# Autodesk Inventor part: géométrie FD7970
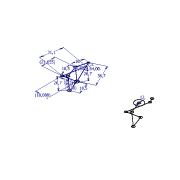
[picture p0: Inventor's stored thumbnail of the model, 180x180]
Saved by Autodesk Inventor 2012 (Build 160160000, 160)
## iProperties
Created: 2011-11
Part Number: géométrie FD7970
Document SubType Name: Modeling
Designer: Laur
Density: 1 g/cm^3
Material: Par défaut
Author: Laur
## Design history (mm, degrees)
sketch "Esquisse1"
  geometry: L1 (278.781, -104.353)-(284.654, -6.929); L2 (284.654, -6.929)-(326.872, -9.474); L3 (326.872, -9.474)-(320.998, -106.898); L4 (320.998, -106.898)-(278.781, -104.353); L5 (-37.691, 5.884)-(39.021, 1.997); L6 (39.021, 1.997)-(37.087, -36.195); L7 (37.087, -36.195)-(-39.625, -32.309); L8 (-39.625, -32.309)-(-37.691, 5.884); L9 (450.184, -16.898)-(444.463, -96.06) reference; L10 (444.463, -96.06)-(405.527, -93.247); L11 (405.527, -93.247)-(411.247, -14.084); L12 (411.247, -14.084)-(450.184, -16.898) reference; L13 (38.92, 0)-(0, 0); L14 (0, 0)-(0, -13.458); L15 (-13.374, -4.322)-(19.75, -20.122); L16 (19.75, -20.122)-(4.255, -24.107); L17 (4.255, -24.107)-(-13.374, -4.322); L18 (-31.711, -6.777)-(-13.374, -4.322); L19 (4.255, -24.107)-(-14.082, -26.562); L20 (-31.711, -6.777)-(-14.082, -26.562); L21 (-13.374, -4.322)-(-6.026, -21.952); L22 (57.013, 4.557)-(57.013, -33.913); L23 (89.022, -33.355)-(84.425, -51.275); L24 (104.427, -68.961)-(84.425, -51.275); L25 (104.427, -68.961)-(109.024, -51.042); L26 (109.024, -51.042)-(91.918, -43.996); L27 (89.022, -33.355)-(109.024, -51.042); L28 (109.024, -51.042)-(93.224, -17.917) reference; L29 (93.224, -17.917)-(89.022, -33.355); L30 (74.805, -79.41)-(127.709, -79.41); L31 (127.709, -79.41)-(127.709, -87.106); L32 (127.709, -87.106)-(74.805, -87.106); L33 (74.805, -87.106)-(74.805, -79.41); L34 (185.107, -90.458)-(185.107, -79.35); L35 (185.107, -79.35)-(238.012, -79.35); L36 (238.012, -79.35)-(238.012, -90.458); L37 (238.012, -90.458)-(185.107, -90.458); L38 (222.335, -68.41)-(215.972, -51.039); L39 (222.335, -68.41)-(202.333, -50.724); L40 (215.972, -51.039)-(197.884, -54.923); L41 (195.97, -33.353)-(202.333, -50.724); L42 (215.972, -51.039)-(200.172, -17.914) reference; L43 (200.172, -17.914)-(195.97, -33.353); L44 (195.97, -33.353)-(215.972, -51.039); L45 (269.3, -80.6)-(269.3, -53.445); L46 (428.304, -32.227)-(422.456, -36.254); L47 (428.304, -32.227)-(420.544, -62.343); L48 (397.895, -41.969)-(397.895, -33.863); L49 (283.808, 9.579)-(278.087, -69.583) reference; L50 (197.884, -54.923)-(203.284, -24.296); L51 (203.284, -24.296)-(200.172, -17.914); L52 (297.728, -27.199)-(303.694, -23.091); L53 (303.694, -23.091)-(295.408, -53.56); L54 (91.918, -43.996)-(98.934, -13.697); L55 (98.934, -13.697)-(93.224, -17.917); L56 (77.02, -96.95)-(237.761, -96.95); L57 (237.761, -96.95)-(237.761, -125.922); L58 (237.761, -125.922)-(77.02, -125.922); L59 (77.02, -125.922)-(77.02, -96.95); C1 r 2.73 at (-13.374, -4.322); C2 r 1.542 at (19.75, -20.122); C3 r 1.924 at (4.255, -24.107); C4 r 2.077 at (-31.711, -6.777); C5 r 1.999 at (-14.082, -26.562); C6 r 1.766 at (-6.026, -21.952); C7 r 1.924 at (89.022, -33.355); C8 r 2.73 at (109.024, -51.042); C9 r 1.999 at (84.425, -51.275); C10 r 2.077 at (104.427, -68.961); C11 r 1.766 at (91.918, -43.996); C12 r 1.542 at (93.224, -17.917); C13 r 2.73 at (215.972, -51.039); C14 r 1.999 at (202.333, -50.724); C15 r 2.077 at (222.335, -68.41); C16 r 1.766 at (197.884, -54.923); C17 r 1.924 at (195.97, -33.353); C18 r 1.542 at (200.172, -17.914); C19 r 1.783 at (295.408, -53.56); C20 r 1.842 at (428.304, -32.227); C21 r 1.928 at (420.544, -62.343); C22 r 1.601 at (422.456, -36.254); C23 r 1.818 at (293.719, -42.271); C24 r 1.92 at (418.558, -50.912); 1 further point; 3 other entities
  constraints: 68 end point, 24 centre point, 2 parallel, 1 coincident, 1 horizontal, 1 perpendicular, 1 point on line, 1 vertical, 21 other
  dimensions: "d12" = 26.5 distance of L16.end L15.start; "d13" = 36.7 distance of L15.end L15.start; "d14" = 16 distance of L16.end L15.end; "d38" = 18.5 distance of L15.start L18.start; "d39" = 18.5 distance of L16.end L19.end; "d40" = 26.5 distance of L19.end L18.start; "d41" = 2.9 deg angle of L5 L13; "d47" = 13.3744 distance from line of L14 L15.start; "d49" = 4.32194 distance from line of L15.start L13; "d52" = 25.5 deg angle of L15 L13; "d71" = 19.1 distance of L21.end L15.start; "d72" = 105 deg angle of L18 L21; "d122" = 34.3062 vertical distance of L7.end L5.end; "d148" = 16 distance of L23.start L28.end; "d149" = 26.7 distance of L25.end L23.start; "d150" = 26.7 distance of L24.start L23.end; "d151" = 18.5 distance of L23.end L23.start; "d152" = 18.5 distance of L24.start L25.end; "d154" = 36.7 distance of L28.end L25.end; "d155" = 18.5 distance of L25.end L26.end; "d186" = 16 distance of L41.start L42.end; "d187" = 26.7 distance of L38.end L41.start; "d188" = 26.7 distance of L38.start L39.end; "d189" = 18.5 distance of L39.end L41.start; "d190" = 18.5 distance of L38.start L38.end; "d191" = 36.7 distance of L42.end L38.end; "d192" = 18.5 distance of L38.end L40.end; "d200" = 3.45 deg angle of L3 L45; "d230" = 97.42345 vertical distance of L3.end L2.end; "d270" = 31.1 distance of L47.end L46.start; "d274" = 7.1 distance of L46.start L46.end; "d276" = 14.45 deg angle of L47 L48; "d278" = 41 deg angle of L47 L46; "d286" = 31.1 distance of L50.end L40.end; "d291" = 7.1 distance of L42.end L50.end; "d292" = 19.78535 vertical distance of L16.end L15.start (derived); "d304" = 40.2361 deg angle of L53 L52; "d307" = 11.41518 distance of L53.end C23.centre; "d308" = 11.60219 distance of L47.end C24.centre; "d310" = 21.65541 distance of L40.end L41.start (derived); "d311" = 31.1 distance of L54.end L26.end; "d312" = 7.1 distance of L28.end L54.end; "d317" = 11.02761 distance of L26.end L23.start (derived); "d319" = 98 deg angle of L25 L26; "d320" = 39.8875 deg angle of L25 L28 (derived); "d321" = 98 deg angle of L38 L40; "d322" = 5.38054 deg angle of L38 L42 (derived); "d323" = 36 deg angle of L50 L51; "d324" = 139.5 deg angle of L54 L55; "d327" = 15.2139 deg angle of L45 L53; "d332" = 24.59875 horizontal distance of L23.end L25.end (derived); "d333" = 18.08767 horizontal distance of L40.end L38.end (derived); "d334" = 53.538 deg angle of L55 L22 (derived); "d337" = 154 deg angle of L51 L22 (derived)
  node "Image1"
  node "Image2"
  node "Image3"
sketch "pos grand plateau" dims "d597" = 12
  geometry: L1 (38.92, 0)-(0, 0); L2 (57.013, 4.557)-(57.013, -33.913); L3 (89.022, -33.355)-(84.425, -51.275); L4 (104.427, -68.961)-(84.425, -51.275); L5 (104.427, -68.961)-(109.024, -51.042); L6 (109.024, -51.042)-(91.918, -43.996); L7 (89.022, -33.355)-(109.024, -51.042); L8 (93.224, -17.917)-(89.022, -33.355); L9 (74.805, -79.41)-(127.709, -79.41); L10 (127.709, -79.41)-(127.709, -87.106); L11 (127.709, -87.106)-(74.805, -87.106); L12 (74.805, -87.106)-(74.805, -79.41); L13 (91.918, -43.996)-(98.934, -13.697); L14 (98.934, -13.697)-(93.224, -17.917); L15 (93.224, -17.917)-(129.229, -17.917); L16 (197.673, -37.138)-(203.902, -10.236); L17 (202.897, -9.569)-(199.93, -11.72); L18 (212.627, -45.195)-(198.906, -39.531); L19 (193.816, -30.061)-(190.132, -44.42); L20 (210.164, -61.991)-(213.847, -47.633); L21 (208.297, -62.564)-(191.009, -47.278); L22 (198.788, -32.172)-(198.817, -32.197); L23 (186.664, -56.328)-(194.774, -56.328); L24 (194.774, -56.328)-(197.613, -53.118); L25 (194.774, -56.328)-(194.774, -65.222); L26 (186.664, -56.328)-(186.664, -65.14); C1 r 1.924 at (89.022, -33.355); C2 r 2.73 at (109.024, -51.042); C3 r 1.999 at (84.425, -51.275); C4 r 2.077 at (104.427, -68.961); C5 r 1.766 at (91.918, -43.996); C6 r 1.542 at (93.224, -17.917); C7 r 1.72 at (98.934, -13.697); A1 r 1.72 centre (204.29, -8.559) between (202.897, -9.569) and (203.902, -10.236); A2 r 1.805 centre (214.295, -45.884) between (212.627, -45.195) and (213.847, -47.633); A3 r 1.766 centre (197.274, -38.858) between (197.673, -37.138) and (198.906, -39.531); A4 r 1.752 centre (189.697, -46.117) between (191.009, -47.278) and (190.132, -44.42); A5 r 1.871 centre (209.699, -63.804) between (210.164, -61.991) and (208.297, -62.564); 3 further points; 1 other entity
  constraints: 44 end point, 12 centre point, 10 point on circle, 4 perpendicular, 2 coincident, 2 point on line, 1 horizontal, 12 other
  dimensions: "d356" = 16 distance of L3.start L8.start; "d357" = 26.7 distance of L5.end L3.start; "d358" = 26.7 distance of L4.start L3.end; "d359" = 18.5 distance of L3.end L3.start; "d360" = 18.5 distance of L4.start L5.end; "d361" = 36.7 distance of L8.start L5.end; "d362" = 18.5 distance of L5.end L6.end; "d383" = 31.1 distance of L13.end L6.end; "d384" = 7.1 distance of L8.start L13.end; "d385" = 11.02761 distance of L6.end L3.start (derived); "d386" = 98 deg angle of L5 L6; "d391" = 139.5 deg angle of L13 L14; "d393" = 24.59875 horizontal distance of L3.end L5.end (derived); "d395" = 53.538 deg angle of L14 L2 (derived); "d571" = 36.462 deg angle of L15 L14
sketch "pos petit plateau"
  geometry: L1 (185.107, -90.458)-(185.107, -79.35); L2 (185.107, -79.35)-(238.012, -79.35); L3 (238.012, -79.35)-(238.012, -90.458); L4 (238.012, -90.458)-(185.107, -90.458); L5 (222.335, -68.41)-(215.972, -51.039); L6 (222.335, -68.41)-(202.333, -50.724); L7 (215.972, -51.039)-(197.884, -54.923); L8 (195.97, -33.353)-(202.333, -50.724); L9 (215.972, -51.039)-(200.172, -17.914) reference; L10 (200.172, -17.914)-(195.97, -33.353); L11 (195.97, -33.353)-(215.972, -51.039); L12 (197.884, -54.923)-(203.284, -24.296); L13 (203.284, -24.296)-(200.172, -17.914); L14 (200.172, -17.914)-(219.448, -17.914); L15 (315.228, -65.819)-(298.28, -50.833); L16 (316.07, -65.245)-(311.102, -51.685); L17 (308.484, -50.24)-(294.059, -53.338); L18 (291.081, -33.944)-(296.095, -47.632); L19 (292.64, -51.97)-(297.432, -24.79); L20 (296.973, -21.521)-(295.434, -18.366); C1 r 2.73 at (215.972, -51.039); C2 r 1.999 at (202.333, -50.724); C3 r 2.077 at (222.335, -68.41); C4 r 1.766 at (197.884, -54.923); C5 r 1.924 at (195.97, -33.353); C6 r 1.542 at (200.172, -17.914); C7 r 6 at (290.419, -32.138); A1 r 2.077 centre (316.784, -67.195) between (315.228, -65.819) and (316.07, -65.245); A2 r 1.766 centre (292.333, -53.708) between (292.64, -51.97) and (294.059, -53.338); A3 r 1.999 centre (296.782, -49.509) between (296.095, -47.632) and (298.28, -50.833); A4 r 1.981 centre (310.421, -49.824) between (308.484, -50.24) and (311.102, -51.685); A5 r 1.735 centre (297.733, -23.081) between (296.973, -21.521) and (297.432, -24.79); 2 further points; 1 other entity
  constraints: 32 end point, 12 centre point, 10 point on circle, 1 coincident, 1 parallel, 10 other
  dimensions: "d427" = 16 distance of L8.start L9.end; "d428" = 26.7 distance of L5.end L8.start; "d429" = 26.7 distance of L5.start L6.end; "d430" = 18.5 distance of L6.end L8.start; "d431" = 18.5 distance of L5.start L5.end; "d432" = 36.7 distance of L9.end L5.end; "d433" = 18.5 distance of L5.end L7.end; "d440" = 31.1 distance of L12.end L7.end; "d441" = 7.1 distance of L9.end L12.end; "d446" = 21.65541 distance of L7.end L8.start (derived); "d452" = 98 deg angle of L5 L7; "d453" = 5.38054 deg angle of L5 L9 (derived); "d454" = 36 deg angle of L12 L13; "d458" = 18.08767 horizontal distance of L7.end L5.end (derived); "d572" = 63.9998 deg angle of L13 L14; "d613" = 12 diameter of C7
sketch "pos calcul"
  geometry: L1 (57.013, 4.557)-(57.013, -33.913); L2 (89.022, -33.355)-(88.049, -51.83); L3 (108.051, -69.516)-(88.049, -51.83); L4 (108.051, -69.516)-(109.024, -51.042); L5 (109.024, -51.042)-(90.865, -47.507); L6 (89.022, -33.355)-(109.024, -51.042); L7 (109.024, -51.042)-(93.224, -17.917) reference; L8 (93.224, -17.917)-(89.022, -33.355); L9 (74.805, -79.41)-(127.709, -79.41); L10 (127.709, -79.41)-(127.709, -87.106); L11 (127.709, -87.106)-(74.805, -87.106); L12 (74.805, -87.106)-(74.805, -79.41); L13 (90.865, -47.507)-(100.324, -17.881); L14 (100.324, -17.881)-(93.224, -17.917); L15 (155.217, -18.333)-(177.365, -18.333); L16 (93.224, -17.917)-(99.657, -19.971); L17 (239.941, -46.723)-(225.668, -43.973); L18 (221.734, -31.443)-(220.999, -45.925); L19 (224.309, -41.688)-(232.504, -15.857); L20 (231.109, -13.986)-(228.008, -13.986); L21 (239.431, -64.249)-(222.398, -49.244); L22 (241.034, -63.574)-(241.767, -49.123); L23 (217.89, -58.102)-(217.89, -66.915); L24 (217.89, -58.102)-(225.999, -58.102); L25 (225.999, -58.102)-(225.999, -66.998); L26 (221.189, -57.55)-(229.225, -57.55); L27 (229.225, -57.55)-(229.225, -66.41); L28 (221.189, -57.55)-(221.189, -66.363); L29 (222.625, -57.548)-(222.625, -66.382); L30 (214.274, -57.548)-(214.274, -66.438); L31 (214.274, -57.548)-(222.625, -57.548); L32 (226.008, -25.513)-(226.008, -14); L33 (219.835, -29.446)-(215.794, -29.446); L34 (215.794, -29.446)-(215.794, -26.693); L35 (215.794, -26.693)-(215.794, -32.379); L36 (241.899, -45.128)-(241.899, -42.134); L37 (241.899, -42.134)-(244.674, -42.134); L38 (244.674, -42.134)-(239.376, -42.134); L39 (215.794, -26.693)-(214.734, -27.897); L40 (215.794, -28.05)-(214.734, -29.254); L41 (215.794, -29.446)-(214.734, -30.65); L42 (215.794, -30.983)-(214.734, -32.187); L43 (215.794, -32.379)-(214.734, -33.582); L44 (244.674, -42.134)-(244.18, -41.098); L45 (243.555, -42.134)-(243.061, -41.098); L46 (242.382, -42.134)-(241.887, -41.098); L47 (241.286, -42.134)-(240.792, -41.098); L48 (240.151, -42.134)-(239.657, -41.098); L49 (227.278, -14)-(227.278, -14.992); L50 (227.278, -14.992)-(226.008, -14.992); L51 (226.008, -14)-(236.582, -6.318); L52 (226.008, -14)-(231.833, -25.942); L53 (199.066, -16.481)-(197.687, -15.267); L54 (199.066, -15.233)-(197.687, -16.481); L55 (224.011, -14.104)-(219.97, -14.104); L56 (219.97, -11.351)-(218.91, -12.555); L57 (219.97, -14.104)-(219.97, -11.351); L58 (219.97, -12.708)-(218.91, -13.912); L59 (219.97, -14.104)-(218.91, -15.308); L60 (219.97, -11.351)-(219.97, -17.037); L61 (219.97, -15.641)-(218.91, -16.845); L62 (219.97, -17.037)-(218.91, -18.241); L63 (225.999, -58.102)-(228.819, -54.901); C1 r 2 at (89.022, -33.355); C2 r 2 at (109.024, -51.042); C3 r 2 at (88.049, -51.83); C4 r 2 at (108.051, -69.516); C5 r 2 at (90.865, -47.507); C6 r 2 at (93.224, -17.917); C7 r 2 at (100.324, -17.881); A1 r 2 centre (223.705, -43.595) between (224.309, -41.688) and (225.668, -43.973); A2 r 2 centre (221.835, -29.446) between (221.734, -31.443) and (219.835, -29.446); A3 r 2 centre (233.108, -13.95) between (231.109, -13.986) and (232.504, -15.857); A4 r 2 centre (220.897, -47.922) between (222.398, -49.244) and (220.999, -45.925); A5 r 2 centre (241.899, -47.128) between (239.941, -46.723) and (241.767, -49.123); A6 r 2 centre (240.932, -65.571) between (241.034, -63.574) and (239.431, -64.249)
  constraints: 118 end point, 18 perpendicular, 17 parallel, 13 centre point, 13 point on circle, 11 point on line, 3 collinear, 1 coincident, 1 horizontal, 7 other
  dimensions: "d480" = 16 distance of L2.start L7.end; "d481" = 26.7 distance of L4.end L2.start; "d482" = 26.7 distance of L3.start L2.end; "d483" = 18.5 distance of L2.end L2.start; "d484" = 18.5 distance of L3.start L4.end; "d485" = 36.7 distance of L7.end L4.end; "d486" = 18.5 distance of L4.end L5.end; "d507" = 31.1 distance of L13.end L5.end; "d508" = 7.1 distance of L7.end L13.end; "d509" = 14.27142 distance of L5.end L2.start (derived); "d510" = 98 deg angle of L4 L5; "d511" = 28.5146 deg angle of L4 L7 (derived); "d515" = 108 deg angle of L13 L14; "d517" = 20.97482 horizontal distance of L2.end L4.end (derived); "d519" = 89.7076 deg angle of L14 L1 (derived); "d534" = 4 diameter of C6; "d535" = 4 diameter of C7 (derived); "d536" = 4 diameter of C1 (derived); "d537" = 4 diameter of C5 (derived); "d538" = 4 diameter of C2 (derived); "d539" = 4 diameter of C4 (derived); "d540" = 4 diameter of C3 (derived); "d542" = 0.29241 deg angle of L15 L14 (derived); "d569" = 6.6 distance between parallel lines of L29 L27; "d570" = 17.6 deg angle of L19 L32; "d573" = 36 deg angle of L20 L51; "d574" = 64 deg angle of L20 L52
node "Corps solides"
node "Corps surfaciques"
